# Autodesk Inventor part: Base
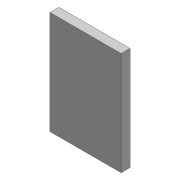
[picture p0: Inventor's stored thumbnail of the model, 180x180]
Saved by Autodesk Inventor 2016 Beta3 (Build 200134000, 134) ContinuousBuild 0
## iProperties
Created: 2016-03
Part Number: Base
Material: Generic
Document SubType Name: Modeling
Designer: Gaurav
Density: 1 g/cm^3
Appearance: Default
Author: Gaurav
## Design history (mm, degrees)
sketch "Sketch1"
  geometry: L1 (125.279, 181.657)-(-125.279, 181.657); L2 (-125.279, 181.657)-(-125.279, -181.657); L3 (-125.279, -181.657)-(125.279, -181.657); L4 (125.279, -181.657)-(125.279, 181.657); L5 (125.279, 181.657)-(-125.279, -181.657); L6 (-125.279, 181.657)-(125.279, -181.657); 1 further point
  constraints: 12 end point, 2 midpoint, 2 parallel, 1 horizontal, 1 perpendicular
extrude "Extrusion1" new body sketch "Sketch1" distance "d0" = 31.25; taper "d1" = 0 deg
sketch "Sketch2"
  geometry: L1 (-65.165, -112.331)-(65.165, -112.331); L2 (70.165, -107.331)-(70.165, 107.331); L3 (65.165, 112.331)-(-65.165, 112.331); L4 (-70.165, 107.331)-(-70.165, -107.331); L5 (-70.165, -112.331)-(70.165, 112.331); L6 (70.165, -112.331)-(-70.165, 112.331); L7 (-75.165, -127.331)-(75.165, -127.331); L8 (85.165, -117.331)-(85.165, 117.331); L9 (75.165, 127.331)-(-75.165, 127.331); L10 (-85.165, 117.331)-(-85.165, -117.331); A1 r 10 centre (75.165, 117.331) between (85.165, 117.331) and (75.165, 127.331); A2 r 10 centre (75.165, -117.331) between (75.165, -127.331) and (85.165, -117.331); A3 r 10 centre (-75.165, -117.331) between (-85.165, -117.331) and (-75.165, -127.331); A4 r 10 centre (-75.165, 117.331) between (-75.165, 127.331) and (-85.165, 117.331); A5 r 5 centre (-65.165, -107.331) between (-70.165, -107.331) and (-65.165, -112.331); A6 r 5 centre (-65.165, 107.331) between (-65.165, 112.331) and (-70.165, 107.331); A7 r 5 centre (65.165, 107.331) between (70.165, 107.331) and (65.165, 112.331); A8 r 5 centre (65.165, -107.331) between (65.165, -112.331) and (70.165, -107.331); 1 further point
  constraints: 20 end point, 16 point on circle, 16 tangent, 8 centre point, 8 point on line, 6 equal radius, 4 parallel, 2 midpoint, 2 perpendicular, 1 horizontal, 3 other
  dimensions: "d2" = 15 distance between parallel lines of L4 L10; "d6" = 10 radius of A1; "d7" = 5 radius of A5
extrude "Extrusion2" cut sketch "Sketch2" distance "d3" = 10; taper "d4" = 0 deg
body "Solid1"
